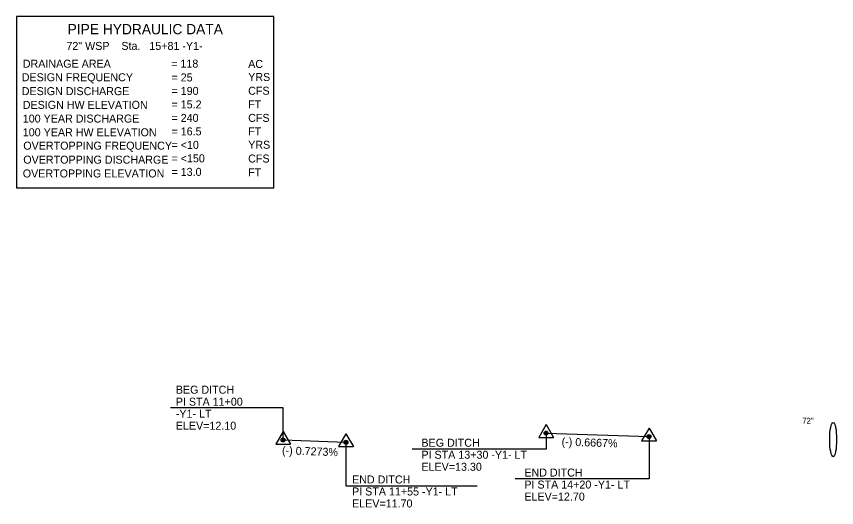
# Model space of a CAD drawing. Extents: x 2179808 to 2190174, y 63168 to 78602.
# Drawn here: x 2179808 to 2180525, y 72159 to 72588 of the extents above; entities that cross this region are included whole.
import ezdxf

# ---------------------------------------------------------------- set-up
doc = ezdxf.new("R2010")
doc.units = 0
for name, color, linetype in [('Default', 7, 'Continuous'), ('Prop Grid Mask', 7, 'Continuous'), ('Prop PFL Cross Pipe CELL', 7, 'Continuous'), ('Prop PFL Cross Pipe Text CELL', 7, 'Continuous'), ('Prop PFL Pipe Hydraulic Data CELL', 7, 'Continuous'), ('Prop Vertical Profile Ditch Grade Left', 7, 'Continuous'), ('Prop Vertical Profile Ditch Grade Left Label', 7, 'Continuous'), ('Prop VPI Ditch Grade Left Label', 7, 'Continuous')]:
    doc.layers.add(name, color=color, linetype=linetype)

msp = doc.modelspace()

# ---------------------------------------------------------------- linework, layer by layer
at = {"layer": 'Default'}
for p, q in [((2180040.9, 72225.26), (2180034.45, 72214.06)), ((2180040.9, 72225.26), (2180047.4, 72214.06)), ((2180270.9, 72231.26), (2180264.45, 72220.06)), ((2180270.9, 72231.26), (2180277.4, 72220.06)), ((2180360.9, 72228.26), (2180354.45, 72217.06)), ((2180360.9, 72228.26), (2180367.4, 72217.06)), ((2180095.9, 72223.26), (2180089.45, 72212.06)), ((2180095.9, 72223.26), (2180102.4, 72212.06)), ((2180264.45, 72220.06), (2180277.4, 72220.06)), ((2180034.45, 72214.06), (2180047.4, 72214.06)), ((2180089.45, 72212.06), (2180102.4, 72212.06)), ((2180354.45, 72217.06), (2180367.4, 72217.06))]:
    msp.add_line(p, q, dxfattribs=at)
for centre, radius in [((2180270.9, 72223.78), 1.75), ((2180040.9, 72217.78), 1.75), ((2180040.9, 72217.78), 1.2), ((2180270.9, 72223.78), 1.2), ((2180360.9, 72220.78), 1.75), ((2180360.9, 72220.78), 1.2), ((2180095.9, 72215.78), 1.75), ((2180095.9, 72215.78), 1.2)]:
    msp.add_circle(centre, radius, dxfattribs=at)
at = {"layer": 'Prop Grid Mask'}
msp.add_lwpolyline([(2179807.75, 72438.36), (2180032.75, 72438.36), (2180032.75, 72588.36), (2179807.75, 72588.36)], close=True, dxfattribs=at)
at = {"layer": 'Prop PFL Cross Pipe CELL'}
msp.add_ellipse((2180521.9, 72218.18), major_axis=(0, 15), ratio=0.2, dxfattribs=at)
at = {"layer": 'Prop Vertical Profile Ditch Grade Left'}
for p, q in [((2180270.9, 72223.78), (2180360.9, 72220.78)), ((2180040.9, 72217.78), (2180095.9, 72215.78))]:
    msp.add_line(p, q, dxfattribs=at)
at = {"layer": 'Prop VPI Ditch Grade Left Label'}
for points in [[(2180040.9, 72217.78), (2180040.9, 72245.94), (2179942.41, 72245.94)], [(2180270.9, 72223.78), (2180270.9, 72209.87), (2180153.74, 72209.87)], [(2180360.9, 72220.78), (2180360.9, 72183.77), (2180243.74, 72183.77)], [(2180095.9, 72215.78), (2180095.9, 72177.73), (2180210.53, 72177.73)]]:
    msp.add_lwpolyline(points, dxfattribs=at)
for centre in [(2180040.9, 72217.78), (2180270.9, 72223.78), (2180360.9, 72220.78), (2180095.9, 72215.78)]:
    msp.add_circle(centre, 0.5, dxfattribs=at)

# ---------------------------------------------------------------- texts
at = {"layer": 'Prop PFL Cross Pipe Text CELL'}
msp.add_text('72"', height=5, dxfattribs=at).set_placement((2180494.97, 72232.17))
at = {"layer": 'Prop PFL Pipe Hydraulic Data CELL'}
for s, height, p in [('PIPE HYDRAULIC DATA', 8.9997, (2179852.55, 72572.71)), ('  72" WSP    Sta.   15+81 -Y1-', 6.9996, (2179846.28, 72559.03)), ('DRAINAGE AREA', 6.9999, (2179813.32, 72543.46)), ('= 118    ', 7, (2179943.11, 72543.53)), ('AC', 7, (2180010.41, 72543.26)), ('DESIGN FREQUENCY', 6.9999, (2179812.42, 72531.61)), ('= 25 ', 7, (2179943.35, 72531.46)), ('YRS', 7, (2180010.41, 72531.86)), ('DESIGN DISCHARGE', 6.9999, (2179812.42, 72519.46)), ('= 190     ', 7, (2179943.35, 72519.66)), ('CFS', 7, (2180010.41, 72519.81)), ('DESIGN HW ELEVATION', 6.9999, (2179813.32, 72507.46)), ('= 15.2    ', 7, (2179943.35, 72507.86)), ('FT', 7, (2180010.41, 72507.86)), ('100 YEAR DISCHARGE', 6.9999, (2179813.32, 72495.46)), ('= 240     ', 7, (2179943.35, 72496.06)), ('CFS', 7, (2180010.41, 72496.06)), ('100 YEAR HW ELEVATION', 6.9999, (2179813.32, 72483.46)), ('= 16.5    ', 7, (2179943.35, 72484.26)), ('FT', 7, (2180010.41, 72484.26)), ('OVERTOPPING FREQUENCY', 6.9999, (2179813.77, 72471.76)), ('= <10', 7, (2179943.35, 72472.46)), ('YRS', 7, (2180010.41, 72472.56)), ('OVERTOPPING DISCHARGE', 6.9999, (2179813.77, 72459.51)), ('= <150    ', 7, (2179943.35, 72460.66)), ('CFS', 7, (2180010.41, 72460.51)), ('OVERTOPPING ELEVATION', 6.9999, (2179813.32, 72447.46)), ('= 13.0    ', 7, (2179943.35, 72448.86)), ('FT', 7, (2180010.41, 72448.46))]:
    msp.add_text(s, height=height, dxfattribs=at).set_placement(p)
at = {"layer": 'Prop Vertical Profile Ditch Grade Left Label'}
for s, rotation, p in [('(-) 0.6667%', 358.09085, (2180284.38, 72212.92)), ('(-) 0.7273%', 357.91743, (2180039.91, 72205.34))]:
    msp.add_text(s, height=7, rotation=rotation, dxfattribs=at).set_placement(p)
at = {"layer": 'Prop VPI Ditch Grade Left Label'}
for s, p in [('BEG DITCH', (2179947.13, 72258.27)), ('PI STA 11+00', (2179947.13, 72247.77)), ('-Y1- LT', (2179947.13, 72237.27)), ('ELEV=12.10', (2179947.13, 72226.77)), ('BEG DITCH', (2180161.9, 72211.87)), ('PI STA 13+30 -Y1- LT', (2180161.9, 72201.37)), ('ELEV=13.30', (2180161.9, 72190.87)), ('END DITCH', (2180251.9, 72185.78)), ('END DITCH', (2180101.25, 72179.73)), ('PI STA 14+20 -Y1- LT', (2180251.9, 72175.28)), ('PI STA 11+55 -Y1- LT', (2180101.25, 72169.23)), ('ELEV=12.70', (2180251.9, 72164.78)), ('ELEV=11.70', (2180101.25, 72158.73))]:
    msp.add_text(s, height=7, dxfattribs=at).set_placement(p)

doc.saveas('drawing.dxf')
